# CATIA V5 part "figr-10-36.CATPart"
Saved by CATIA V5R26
Part number: Part1
Bounding box of the stored display mesh (mm): x -85.282 to 128.744, y -7.97 to 191.596, z 0 to 148.964
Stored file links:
  D:\_Deepak\CATIA\CATIA V5-6R2016_Deepak\Resources\Part files\Partfiles\c10_catia_v5_6r2016_prt\figr-10-36.CATPart
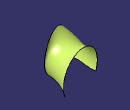
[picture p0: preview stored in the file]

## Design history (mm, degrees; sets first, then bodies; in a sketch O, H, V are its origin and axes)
Set1
  Sketch1 on xy-plane, origin (0, 0, 0), H (1, 0, 0), V (0, 1, 0)
    spline S1 through (-60, 0) (-70, 70) (-70, 170) (-80, 190)
  Sketch2 on yz-plane, origin (0, 0, 0), H (0, 1, 0), V (0, 0, 1)
    spline S1 through (0, 170) (100, 120) (180, 150)
  Sketch3 on xy-plane, origin (0, 0, 0), H (1, 0, 0), V (0, 1, 0)
    spline S1 through (70, 0) (70, 80) (120, 190)
  Sweep1: type Circle, Guide (Sketch1; Sketch2; Sketch3)
Body1 (main body)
